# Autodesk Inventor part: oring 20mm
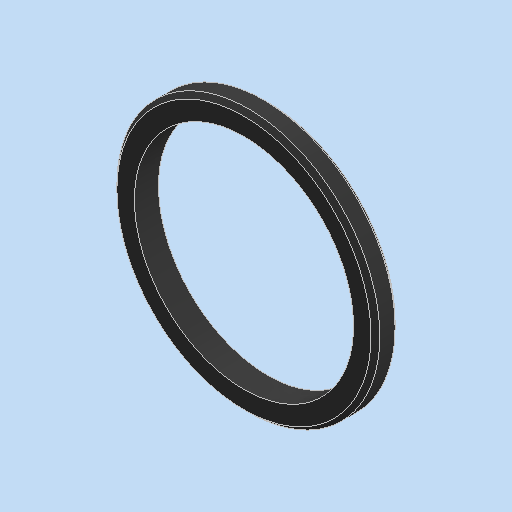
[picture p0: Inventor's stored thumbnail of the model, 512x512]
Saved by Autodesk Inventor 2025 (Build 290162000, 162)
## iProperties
Created: 2025-04
Part Number: oring 20mm
Material: Gomma
Document SubType Name: Modeling
Designer: R5800u
Density: 0.93 g/cm^3
Appearance: Gomma - Nero
Author: R5800u
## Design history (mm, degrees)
sketch "Schizzo1"
  geometry: C1 r 10 at (0, 0); C2 r 12 at (0, 0); 1 further point
  constraints: 2 centre point, 2 coincident
  dimensions: "d0" = 20 diameter of C1; "d1" = 24 diameter of C2
extrude "Estrusione1" new body sketch "Schizzo1" distance "d2" = 2.2; taper "d3" = 0 deg
chamfer "Smusso1" distance "d4" = 0.4; stored, may be unused: second distance "d5" = 2, angle "d6" = 45 deg
node "Solido1"
